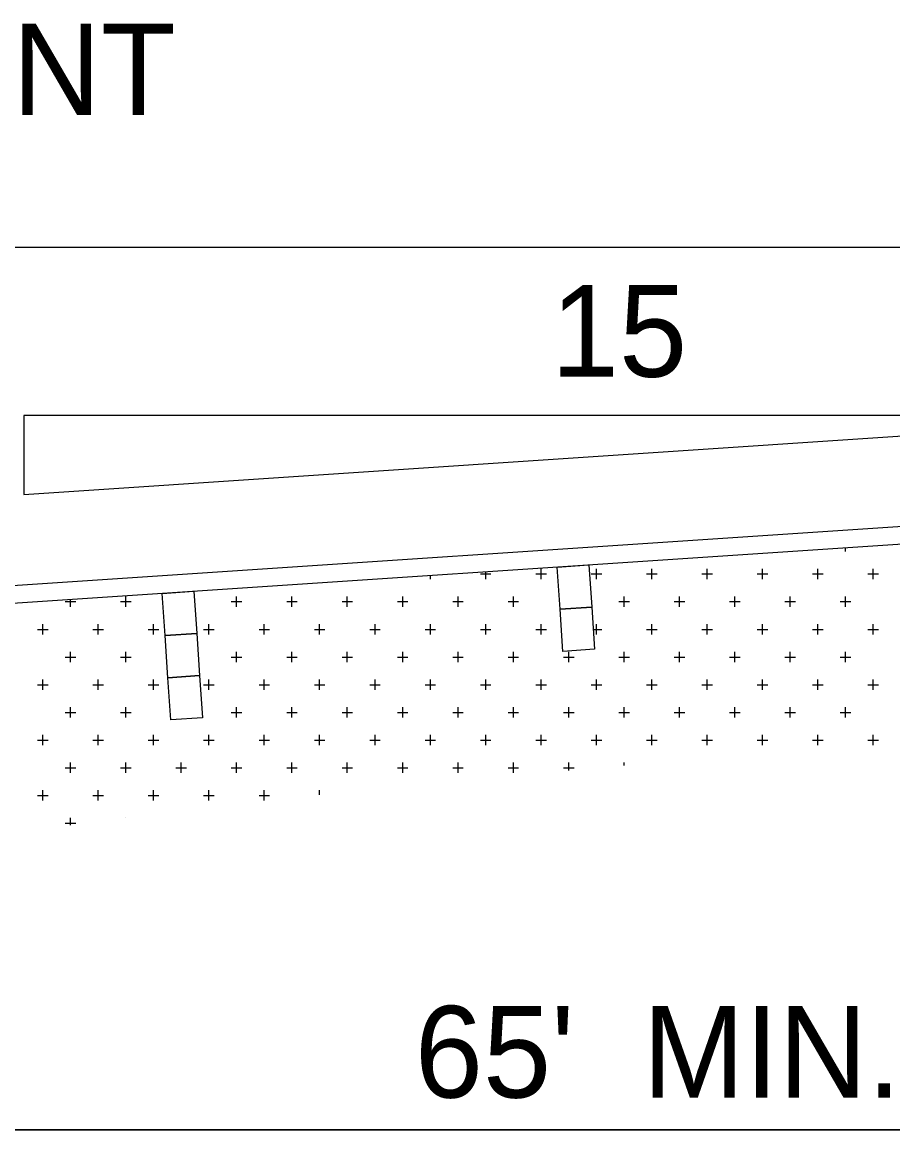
# Model space of a CAD drawing. Extents: x 1312564.5 to 1312581.5, y 1207298.4 to 1207309.4.
# Drawn here: x 1312567.489 to 1312568.249, y 1207302.405 to 1207303.373 of the extents above; entities that cross this region are included whole.
import ezdxf

# ---------------------------------------------------------------- set-up
doc = ezdxf.new("R2010")
doc.units = 0
for name, color, linetype in [('Level 15', 7, 'Continuous'), ('Level 2', 7, 'Continuous'), ('Level 20', 7, 'Continuous'), ('Level 3', 7, 'Continuous'), ('Level 4', 7, 'Continuous')]:
    doc.layers.add(name, color=color, linetype=linetype)

msp = doc.modelspace()

# ---------------------------------------------------------------- linework, layer by layer
at = {"layer": 'Level 15'}
for p, q in [((1312567.49019, 1207303.02928), (1312567.49019, 1207302.96016)), ((1312567.49019, 1207302.96016), (1312568.52699, 1207303.02928)), ((1312568.52699, 1207303.02928), (1312567.49019, 1207303.02928)), ((1312569.4466, 1207302.40549), (1312565.7882, 1207302.40549))]:
    msp.add_line(p, q, dxfattribs=at)
msp.add_lwpolyline([(1312566.11618, 1207302.40549), (1312569.4466, 1207302.40549)], dxfattribs=at)
at = {"layer": 'Level 2'}
for p, q in [((1312570.19519, 1207303.06143), (1312566.91178, 1207302.84253)), ((1312570.19519, 1207303.04613), (1312566.9128, 1207302.8273))]:
    msp.add_line(p, q, dxfattribs=at)
for points in [[(1312567.95592, 1207302.89684), (1312567.9835, 1207302.89868), (1312567.98595, 1207302.8619), (1312567.95837, 1207302.86006)], [(1312567.61108, 1207302.87385), (1312567.63867, 1207302.87569), (1312567.64112, 1207302.83891), (1312567.61353, 1207302.83707)], [(1312567.95837, 1207302.86006), (1312567.98595, 1207302.8619), (1312567.98841, 1207302.82512), (1312567.96082, 1207302.82328)], [(1312567.61353, 1207302.83707), (1312567.64112, 1207302.83891), (1312567.64357, 1207302.80213), (1312567.61599, 1207302.80029)], [(1312567.61599, 1207302.80029), (1312567.64357, 1207302.80213), (1312567.64602, 1207302.76535), (1312567.61844, 1207302.76351)]]:
    msp.add_lwpolyline(points, close=True, dxfattribs=at)
at = {"layer": 'Level 3'}
msp.add_line((1312570.19519, 1207303.1759), (1312565.7882, 1207303.1759), dxfattribs=at)
at = {"layer": 'Level 4'}
for p, q in [((1312568.20753, 1207302.91038), (1312568.20753, 1207302.91362)), ((1312568.1592, 1207302.91038), (1312568.1592, 1207302.9104)), ((1312567.94173, 1207302.88622), (1312567.94173, 1207302.89543)), ((1312567.99006, 1207302.88622), (1312567.99006, 1207302.89543)), ((1312568.03838, 1207302.88622), (1312568.03838, 1207302.89543)), ((1312568.08671, 1207302.88622), (1312568.08671, 1207302.89543)), ((1312568.13504, 1207302.88622), (1312568.13504, 1207302.89543)), ((1312568.18336, 1207302.88622), (1312568.18336, 1207302.89543)), ((1312568.23169, 1207302.88622), (1312568.23169, 1207302.89543)), ((1312567.79675, 1207302.88622), (1312567.79675, 1207302.88623)), ((1312567.84508, 1207302.88622), (1312567.84508, 1207302.88945)), ((1312567.88879, 1207302.89082), (1312567.89801, 1207302.89082)), ((1312567.8934, 1207302.88622), (1312567.8934, 1207302.89268)), ((1312567.93712, 1207302.89082), (1312567.94634, 1207302.89082)), ((1312567.98545, 1207302.89082), (1312567.99466, 1207302.89082)), ((1312568.03378, 1207302.89082), (1312568.04299, 1207302.89082)), ((1312568.0821, 1207302.89082), (1312568.09132, 1207302.89082)), ((1312568.13043, 1207302.89082), (1312568.13965, 1207302.89082)), ((1312568.17875, 1207302.89082), (1312568.18797, 1207302.89082)), ((1312568.22708, 1207302.89082), (1312568.2363, 1207302.89082)), ((1312567.52634, 1207302.86666), (1312567.53556, 1207302.86666)), ((1312567.53095, 1207302.86666), (1312567.53095, 1207302.86851)), ((1312567.53095, 1207302.86206), (1312567.53095, 1207302.86666)), ((1312567.57467, 1207302.86666), (1312567.57928, 1207302.86666)), ((1312567.57927, 1207302.86666), (1312567.57927, 1207302.87127)), ((1312567.57927, 1207302.86666), (1312567.58388, 1207302.86666)), ((1312567.57928, 1207302.86206), (1312567.57928, 1207302.86666)), ((1312567.67132, 1207302.86666), (1312567.68054, 1207302.86666)), ((1312567.67593, 1207302.86666), (1312567.67593, 1207302.87127)), ((1312567.67593, 1207302.86206), (1312567.67593, 1207302.86666)), ((1312567.71965, 1207302.86666), (1312567.72887, 1207302.86666)), ((1312567.72426, 1207302.86666), (1312567.72426, 1207302.87127)), ((1312567.72426, 1207302.86206), (1312567.72426, 1207302.86666)), ((1312567.76798, 1207302.86666), (1312567.77719, 1207302.86666)), ((1312567.77259, 1207302.86666), (1312567.77259, 1207302.87127)), ((1312567.77259, 1207302.86206), (1312567.77259, 1207302.86666)), ((1312567.8163, 1207302.86666), (1312567.82552, 1207302.86666)), ((1312567.82091, 1207302.86666), (1312567.82091, 1207302.87127)), ((1312567.82091, 1207302.86206), (1312567.82091, 1207302.86666)), ((1312567.86463, 1207302.86666), (1312567.86924, 1207302.86666)), ((1312567.86924, 1207302.86666), (1312567.86924, 1207302.87127)), ((1312567.86924, 1207302.86206), (1312567.86924, 1207302.86666)), ((1312567.86924, 1207302.86666), (1312567.87384, 1207302.86666)), ((1312567.91296, 1207302.86666), (1312567.92217, 1207302.86666)), ((1312567.91756, 1207302.86666), (1312567.91756, 1207302.87127)), ((1312567.91756, 1207302.86206), (1312567.91756, 1207302.86666)), ((1312568.00961, 1207302.86666), (1312568.01883, 1207302.86666)), ((1312568.01422, 1207302.86666), (1312568.01422, 1207302.87127)), ((1312568.01422, 1207302.86206), (1312568.01422, 1207302.86666)), ((1312568.05794, 1207302.86666), (1312568.06716, 1207302.86666)), ((1312568.06255, 1207302.86666), (1312568.06255, 1207302.87127)), ((1312568.06255, 1207302.86206), (1312568.06255, 1207302.86666)), ((1312568.10627, 1207302.86666), (1312568.11548, 1207302.86666)), ((1312568.11088, 1207302.86666), (1312568.11088, 1207302.87127)), ((1312568.11088, 1207302.86206), (1312568.11088, 1207302.86666)), ((1312568.1546, 1207302.86666), (1312568.1592, 1207302.86666)), ((1312568.1592, 1207302.86666), (1312568.1592, 1207302.87127)), ((1312568.1592, 1207302.86206), (1312568.1592, 1207302.86666)), ((1312568.1592, 1207302.86666), (1312568.16381, 1207302.86666)), ((1312568.20292, 1207302.86666), (1312568.21213, 1207302.86666)), ((1312568.20753, 1207302.86666), (1312568.20753, 1207302.87127)), ((1312568.20753, 1207302.86206), (1312568.20753, 1207302.86666)), ((1312567.50679, 1207302.83789), (1312567.50679, 1207302.84711)), ((1312567.55511, 1207302.83789), (1312567.55511, 1207302.84711)), ((1312567.60344, 1207302.83789), (1312567.60344, 1207302.84711)), ((1312567.65177, 1207302.83789), (1312567.65177, 1207302.84711)), ((1312567.70009, 1207302.83789), (1312567.70009, 1207302.84711)), ((1312567.74842, 1207302.83789), (1312567.74842, 1207302.84711)), ((1312567.79675, 1207302.83789), (1312567.79675, 1207302.84711)), ((1312567.84508, 1207302.83789), (1312567.84508, 1207302.84711)), ((1312567.8934, 1207302.83789), (1312567.8934, 1207302.84711)), ((1312567.94173, 1207302.83789), (1312567.94173, 1207302.84711)), ((1312567.99006, 1207302.83789), (1312567.99006, 1207302.84711)), ((1312568.03838, 1207302.83789), (1312568.03838, 1207302.84711)), ((1312568.08671, 1207302.83789), (1312568.08671, 1207302.84711)), ((1312568.13504, 1207302.83789), (1312568.13504, 1207302.84711)), ((1312568.18336, 1207302.83789), (1312568.18336, 1207302.84711)), ((1312568.23169, 1207302.83789), (1312568.23169, 1207302.84711)), ((1312567.50218, 1207302.8425), (1312567.51139, 1207302.8425)), ((1312567.55051, 1207302.8425), (1312567.55972, 1207302.8425)), ((1312567.59883, 1207302.8425), (1312567.60805, 1207302.8425)), ((1312567.64716, 1207302.8425), (1312567.65637, 1207302.8425)), ((1312567.69549, 1207302.8425), (1312567.7047, 1207302.8425)), ((1312567.74381, 1207302.8425), (1312567.75303, 1207302.8425)), ((1312567.79214, 1207302.8425), (1312567.80136, 1207302.8425)), ((1312567.84047, 1207302.8425), (1312567.84968, 1207302.8425)), ((1312567.88879, 1207302.8425), (1312567.89801, 1207302.8425)), ((1312567.93712, 1207302.8425), (1312567.94634, 1207302.8425)), ((1312567.98725, 1207302.8425), (1312567.99466, 1207302.8425)), ((1312568.03378, 1207302.8425), (1312568.04299, 1207302.8425)), ((1312568.0821, 1207302.8425), (1312568.09132, 1207302.8425)), ((1312568.13043, 1207302.8425), (1312568.13965, 1207302.8425)), ((1312568.17875, 1207302.8425), (1312568.18797, 1207302.8425)), ((1312568.22708, 1207302.8425), (1312568.2363, 1207302.8425)), ((1312567.52634, 1207302.81834), (1312567.53556, 1207302.81834)), ((1312567.53095, 1207302.81373), (1312567.53095, 1207302.82294)), ((1312567.57467, 1207302.81834), (1312567.57928, 1207302.81834)), ((1312567.57927, 1207302.81373), (1312567.57927, 1207302.82294)), ((1312567.57927, 1207302.81834), (1312567.58388, 1207302.81834)), ((1312567.67132, 1207302.81834), (1312567.68054, 1207302.81834)), ((1312567.67593, 1207302.81373), (1312567.67593, 1207302.82294)), ((1312567.71965, 1207302.81834), (1312567.72887, 1207302.81834)), ((1312567.72426, 1207302.81373), (1312567.72426, 1207302.82294)), ((1312567.76798, 1207302.81834), (1312567.77719, 1207302.81834)), ((1312567.77259, 1207302.81373), (1312567.77259, 1207302.82294)), ((1312567.8163, 1207302.81834), (1312567.82552, 1207302.81834)), ((1312567.82091, 1207302.81373), (1312567.82091, 1207302.82294)), ((1312567.86463, 1207302.81834), (1312567.86924, 1207302.81834)), ((1312567.86924, 1207302.81373), (1312567.86924, 1207302.82294)), ((1312567.86924, 1207302.81834), (1312567.87384, 1207302.81834)), ((1312567.91296, 1207302.81834), (1312567.92217, 1207302.81834)), ((1312567.91756, 1207302.81373), (1312567.91756, 1207302.82294)), ((1312567.96128, 1207302.81834), (1312567.9705, 1207302.81834)), ((1312567.96589, 1207302.81373), (1312567.96589, 1207302.82294)), ((1312568.00961, 1207302.81834), (1312568.01883, 1207302.81834)), ((1312568.01422, 1207302.81373), (1312568.01422, 1207302.82294)), ((1312568.05794, 1207302.81834), (1312568.06716, 1207302.81834)), ((1312568.06255, 1207302.81373), (1312568.06255, 1207302.82294)), ((1312568.10627, 1207302.81834), (1312568.11548, 1207302.81834)), ((1312568.11088, 1207302.81373), (1312568.11088, 1207302.82294)), ((1312568.1546, 1207302.81834), (1312568.1592, 1207302.81834)), ((1312568.1592, 1207302.81373), (1312568.1592, 1207302.82294)), ((1312568.1592, 1207302.81834), (1312568.16381, 1207302.81834)), ((1312568.20292, 1207302.81834), (1312568.21213, 1207302.81834)), ((1312568.20753, 1207302.81373), (1312568.20753, 1207302.82294)), ((1312567.50679, 1207302.78956), (1312567.50679, 1207302.79878)), ((1312567.55511, 1207302.78956), (1312567.55511, 1207302.79878)), ((1312567.60344, 1207302.78956), (1312567.60344, 1207302.79878)), ((1312567.65177, 1207302.78956), (1312567.65177, 1207302.79878)), ((1312567.70009, 1207302.78956), (1312567.70009, 1207302.79878)), ((1312567.74842, 1207302.78956), (1312567.74842, 1207302.79878)), ((1312567.79675, 1207302.78956), (1312567.79675, 1207302.79878)), ((1312567.84508, 1207302.78956), (1312567.84508, 1207302.79878)), ((1312567.8934, 1207302.78956), (1312567.8934, 1207302.79878)), ((1312567.94173, 1207302.78956), (1312567.94173, 1207302.79878)), ((1312567.99006, 1207302.78956), (1312567.99006, 1207302.79878)), ((1312568.03838, 1207302.78956), (1312568.03838, 1207302.79878)), ((1312568.08671, 1207302.78956), (1312568.08671, 1207302.79878)), ((1312568.13504, 1207302.78956), (1312568.13504, 1207302.79878)), ((1312568.18336, 1207302.78956), (1312568.18336, 1207302.79878)), ((1312568.23169, 1207302.78956), (1312568.23169, 1207302.79878)), ((1312567.50218, 1207302.79417), (1312567.51139, 1207302.79417)), ((1312567.55051, 1207302.79417), (1312567.55972, 1207302.79417)), ((1312567.59883, 1207302.79417), (1312567.60805, 1207302.79417)), ((1312567.64716, 1207302.79417), (1312567.65637, 1207302.79417)), ((1312567.69549, 1207302.79417), (1312567.7047, 1207302.79417)), ((1312567.74381, 1207302.79417), (1312567.75303, 1207302.79417)), ((1312567.79214, 1207302.79417), (1312567.80136, 1207302.79417)), ((1312567.84047, 1207302.79417), (1312567.84968, 1207302.79417)), ((1312567.88879, 1207302.79417), (1312567.89801, 1207302.79417)), ((1312567.93712, 1207302.79417), (1312567.94634, 1207302.79417)), ((1312567.98545, 1207302.79417), (1312567.99466, 1207302.79417)), ((1312568.03378, 1207302.79417), (1312568.04299, 1207302.79417)), ((1312568.0821, 1207302.79417), (1312568.09132, 1207302.79417)), ((1312568.13043, 1207302.79417), (1312568.13965, 1207302.79417)), ((1312568.17875, 1207302.79417), (1312568.18797, 1207302.79417)), ((1312568.22708, 1207302.79417), (1312568.2363, 1207302.79417)), ((1312567.52634, 1207302.77001), (1312567.53556, 1207302.77001)), ((1312567.53095, 1207302.7654), (1312567.53095, 1207302.77462)), ((1312567.57467, 1207302.77001), (1312567.57928, 1207302.77001)), ((1312567.57927, 1207302.7654), (1312567.57927, 1207302.77462)), ((1312567.57927, 1207302.77001), (1312567.58388, 1207302.77001)), ((1312567.67132, 1207302.77001), (1312567.68054, 1207302.77001)), ((1312567.67593, 1207302.7654), (1312567.67593, 1207302.77462)), ((1312567.71965, 1207302.77001), (1312567.72887, 1207302.77001)), ((1312567.72426, 1207302.7654), (1312567.72426, 1207302.77462)), ((1312567.76798, 1207302.77001), (1312567.77719, 1207302.77001)), ((1312567.77259, 1207302.7654), (1312567.77259, 1207302.77462)), ((1312567.8163, 1207302.77001), (1312567.82552, 1207302.77001)), ((1312567.82091, 1207302.7654), (1312567.82091, 1207302.77462)), ((1312567.86463, 1207302.77001), (1312567.86924, 1207302.77001)), ((1312567.86924, 1207302.7654), (1312567.86924, 1207302.77462)), ((1312567.86924, 1207302.77001), (1312567.87384, 1207302.77001)), ((1312567.91296, 1207302.77001), (1312567.92217, 1207302.77001)), ((1312567.91756, 1207302.7654), (1312567.91756, 1207302.77462)), ((1312567.96128, 1207302.77001), (1312567.9705, 1207302.77001)), ((1312567.96589, 1207302.7654), (1312567.96589, 1207302.77462)), ((1312568.00961, 1207302.77001), (1312568.01883, 1207302.77001)), ((1312568.01422, 1207302.7654), (1312568.01422, 1207302.77462)), ((1312568.05794, 1207302.77001), (1312568.06716, 1207302.77001)), ((1312568.06255, 1207302.7654), (1312568.06255, 1207302.77462)), ((1312568.10627, 1207302.77001), (1312568.11548, 1207302.77001)), ((1312568.11088, 1207302.7654), (1312568.11088, 1207302.77462)), ((1312568.1546, 1207302.77001), (1312568.1592, 1207302.77001)), ((1312568.1592, 1207302.7654), (1312568.1592, 1207302.77462)), ((1312568.1592, 1207302.77001), (1312568.16381, 1207302.77001)), ((1312568.20292, 1207302.77001), (1312568.21213, 1207302.77001)), ((1312568.20753, 1207302.7654), (1312568.20753, 1207302.77462)), ((1312567.50679, 1207302.74124), (1312567.50679, 1207302.75045)), ((1312567.55511, 1207302.74124), (1312567.55511, 1207302.75045)), ((1312567.60344, 1207302.74124), (1312567.60344, 1207302.75045)), ((1312567.65177, 1207302.74124), (1312567.65177, 1207302.75045)), ((1312567.70009, 1207302.74124), (1312567.70009, 1207302.75045)), ((1312567.74842, 1207302.74124), (1312567.74842, 1207302.75045)), ((1312567.79675, 1207302.74124), (1312567.79675, 1207302.75045)), ((1312567.84508, 1207302.74124), (1312567.84508, 1207302.75045)), ((1312567.8934, 1207302.74124), (1312567.8934, 1207302.75045)), ((1312567.94173, 1207302.74124), (1312567.94173, 1207302.75045)), ((1312567.99006, 1207302.74124), (1312567.99006, 1207302.75045)), ((1312568.03838, 1207302.74124), (1312568.03838, 1207302.75045)), ((1312568.08671, 1207302.74124), (1312568.08671, 1207302.75045)), ((1312568.13504, 1207302.74124), (1312568.13504, 1207302.75045)), ((1312568.18336, 1207302.74124), (1312568.18336, 1207302.75045)), ((1312568.23169, 1207302.74124), (1312568.23169, 1207302.75045)), ((1312567.50218, 1207302.74584), (1312567.51139, 1207302.74584)), ((1312567.55051, 1207302.74584), (1312567.55972, 1207302.74584)), ((1312567.59883, 1207302.74584), (1312567.60805, 1207302.74584)), ((1312567.64716, 1207302.74584), (1312567.65637, 1207302.74584)), ((1312567.69549, 1207302.74584), (1312567.7047, 1207302.74584)), ((1312567.74381, 1207302.74584), (1312567.75303, 1207302.74584)), ((1312567.79214, 1207302.74584), (1312567.80136, 1207302.74584)), ((1312567.84047, 1207302.74584), (1312567.84968, 1207302.74584)), ((1312567.88879, 1207302.74584), (1312567.89801, 1207302.74584)), ((1312567.93712, 1207302.74584), (1312567.94634, 1207302.74584)), ((1312567.98545, 1207302.74584), (1312567.99466, 1207302.74584)), ((1312568.03378, 1207302.74584), (1312568.04299, 1207302.74584)), ((1312568.0821, 1207302.74584), (1312568.09132, 1207302.74584)), ((1312568.13043, 1207302.74584), (1312568.13965, 1207302.74584)), ((1312568.17875, 1207302.74584), (1312568.18797, 1207302.74584)), ((1312568.22708, 1207302.74584), (1312568.2363, 1207302.74584)), ((1312567.52634, 1207302.72168), (1312567.53556, 1207302.72168)), ((1312567.53095, 1207302.71707), (1312567.53095, 1207302.72629)), ((1312567.57467, 1207302.72168), (1312567.57928, 1207302.72168)), ((1312567.57927, 1207302.71707), (1312567.57927, 1207302.72629)), ((1312567.57927, 1207302.72168), (1312567.58388, 1207302.72168)), ((1312567.62299, 1207302.72168), (1312567.63221, 1207302.72168)), ((1312567.6276, 1207302.71707), (1312567.6276, 1207302.72629)), ((1312567.67132, 1207302.72168), (1312567.68054, 1207302.72168)), ((1312567.67593, 1207302.71707), (1312567.67593, 1207302.72629)), ((1312567.71965, 1207302.72168), (1312567.72887, 1207302.72168)), ((1312567.72426, 1207302.71707), (1312567.72426, 1207302.72629)), ((1312567.76798, 1207302.72168), (1312567.77719, 1207302.72168)), ((1312567.77259, 1207302.71707), (1312567.77259, 1207302.72629)), ((1312567.8163, 1207302.72168), (1312567.82552, 1207302.72168)), ((1312567.82091, 1207302.71707), (1312567.82091, 1207302.72629)), ((1312567.86463, 1207302.72168), (1312567.86924, 1207302.72168)), ((1312567.86924, 1207302.71707), (1312567.86924, 1207302.72629)), ((1312567.86924, 1207302.72168), (1312567.87384, 1207302.72168)), ((1312567.91296, 1207302.72168), (1312567.92217, 1207302.72168)), ((1312567.91756, 1207302.71707), (1312567.91756, 1207302.72629)), ((1312567.96128, 1207302.72168), (1312567.9705, 1207302.72168)), ((1312567.96589, 1207302.71934), (1312567.96589, 1207302.72629)), ((1312568.01422, 1207302.72361), (1312568.01422, 1207302.72629)), ((1312567.50679, 1207302.69291), (1312567.50679, 1207302.70212)), ((1312567.55511, 1207302.69291), (1312567.55511, 1207302.70212)), ((1312567.60344, 1207302.69291), (1312567.60344, 1207302.70212)), ((1312567.65177, 1207302.69291), (1312567.65177, 1207302.70212)), ((1312567.70009, 1207302.69291), (1312567.70009, 1207302.70212)), ((1312567.74842, 1207302.69786), (1312567.74842, 1207302.70212)), ((1312567.50218, 1207302.69752), (1312567.51139, 1207302.69752)), ((1312567.55051, 1207302.69752), (1312567.55972, 1207302.69752)), ((1312567.59883, 1207302.69752), (1312567.60805, 1207302.69752)), ((1312567.64716, 1207302.69752), (1312567.65637, 1207302.69752)), ((1312567.69549, 1207302.69752), (1312567.7047, 1207302.69752)), ((1312567.52634, 1207302.67335), (1312567.53556, 1207302.67335)), ((1312567.53095, 1207302.67155), (1312567.53095, 1207302.67796)), ((1312567.57927, 1207302.67791), (1312567.57927, 1207302.67796))]:
    msp.add_line(p, q, dxfattribs=at)

# ---------------------------------------------------------------- texts
at = {"layer": 'Level 15'}
msp.add_text('15', height=0.08, dxfattribs=at).set_placement((1312567.95027, 1207303.06301))
at = {"layer": 'Level 20'}
for s, p in [('EDGE OF PAVEMENT', (1312566.52313, 1207303.29145)), ("65'  MIN.", (1312567.83151, 1207302.43367))]:
    msp.add_text(s, height=0.08, dxfattribs=at).set_placement(p)

doc.saveas('drawing.dxf')
